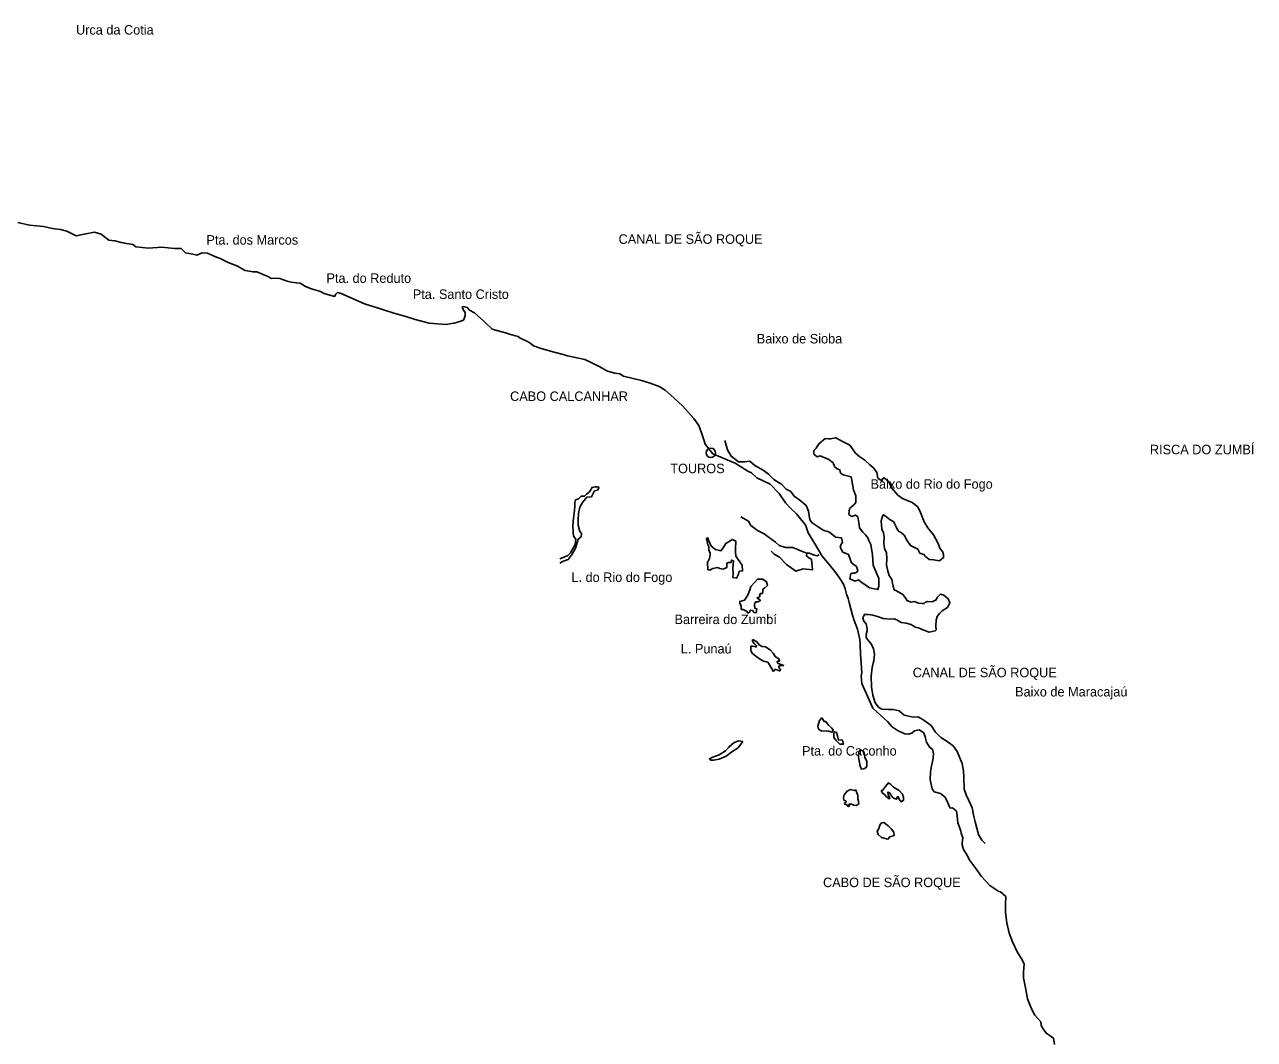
# Model space of a CAD drawing. Extents: x 662444 to 1640468, y 7452018 to 9606170.
# Drawn here: x 1512526 to 1601826, y 9374367 to 9448070 of the extents above; entities that cross this region are included whole.
import ezdxf

# ---------------------------------------------------------------- set-up
doc = ezdxf.new("R2010")
doc.units = 0
for name, color, linetype in [('Level 1', 7, 'Continuous'), ('Level 2', 7, 'Continuous'), ('Level 3', 7, 'Continuous')]:
    doc.layers.add(name, color=color, linetype=linetype)

msp = doc.modelspace()

# ---------------------------------------------------------------- linework, layer by layer
at = {"layer": 'Level 1'}
for points in [[(1520377, 9432099), (1519785, 9432206), (1519542, 9432234), (1519080, 9432354), (1518651, 9432419), (1518079, 9432850), (1517601, 9432988), (1516853, 9432845), (1516274, 9432734), (1515588, 9433061), (1515134, 9433190), (1514558, 9433272), (1513894, 9433397), (1512889, 9433503), (1512046, 9433703)], [(1551627, 9424102), (1550980, 9424279), (1550042, 9424555), (1549476, 9424735), (1549203, 9424960), (1548945, 9425111), (1548501, 9425296), (1548372, 9425413), (1548169, 9425457), (1547806, 9425552), (1547450, 9425672), (1546908, 9425828), (1546487, 9425956), (1545878, 9426520), (1545198, 9427125), (1544834, 9427326), (1544667, 9427517), (1544392, 9427594), (1544302, 9427555), (1544404, 9427326), (1544523, 9427168), (1544527, 9426924), (1544392, 9426592), (1544064, 9426476), (1543689, 9426384), (1543119, 9426287), (1541909, 9426388), (1540897, 9426648), (1540129, 9426905), (1539344, 9427104), (1538374, 9427430), (1537209, 9427798), (1535514, 9428549), (1535239, 9428611), (1535131, 9428482), (1535031, 9428329), (1534279, 9428545), (1534004, 9428688), (1533358, 9428869), (1532929, 9429054), (1532543, 9429297), (1532244, 9429326), (1531878, 9429364), (1531595, 9429425), (1531070, 9429629), (1530802, 9429650), (1530452, 9429639), (1530138, 9429807), (1529395, 9430103), (1529119, 9430107), (1528551, 9430222), (1527947, 9430558), (1527309, 9430788), (1526721, 9431089), (1526341, 9431226), (1525809, 9431478), (1525419, 9431484), (1525034, 9431320), (1524743, 9431389), (1524209, 9431503), (1523888, 9431801), (1523400, 9431809), (1522484, 9431913), (1521524, 9431838), (1520599, 9431917), (1520377, 9432099)], [(1571455, 9408225), (1570849, 9408977), (1570451, 9409465), (1569882, 9410403), (1569415, 9411153), (1569230, 9411742), (1568967, 9412048), (1568568, 9412544), (1568143, 9412942), (1567784, 9413347), (1567308, 9414015), (1566661, 9414694), (1565701, 9415159), (1565317, 9415523), (1565034, 9415642), (1564117, 9416219), (1562510, 9416898), (1561944, 9417592), (1561851, 9417903), (1561689, 9418426), (1561487, 9418952), (1561130, 9419455), (1560332, 9420356), (1559666, 9420953), (1559033, 9421518), (1558615, 9421785), (1557960, 9422024), (1557321, 9422229), (1556009, 9422536), (1555744, 9422695), (1555386, 9422742), (1554860, 9422897), (1554239, 9423233), (1553659, 9423535), (1553207, 9423738), (1551959, 9424011), (1551627, 9424102)], [(1563368, 9417866), (1563558, 9417185), (1563825, 9416722), (1564369, 9416319), (1564833, 9416310), (1565184, 9416352), (1565543, 9416042), (1566146, 9415720), (1566538, 9415426), (1566937, 9415027), (1567507, 9414664), (1567818, 9414339), (1568164, 9414169), (1568401, 9413829), (1568818, 9413519), (1569282, 9413151), (1569444, 9412739), (1569552, 9412099), (1569711, 9411876), (1570521, 9411344), (1570974, 9411197), (1571413, 9410845), (1571835, 9410796), (1571918, 9410450), (1571818, 9410338), (1571756, 9410111), (1571952, 9409763), (1572355, 9409584), (1572578, 9408983), (1572930, 9408706), (1573030, 9408427), (1572946, 9408298), (1572782, 9408235), (1572644, 9408239), (1572513, 9408200), (1572457, 9407817), (1572836, 9407654), (1573074, 9407748), (1573249, 9407589), (1573715, 9407286), (1573883, 9407168), (1574222, 9407087), (1574442, 9407067), (1574490, 9407049), (1574544, 9407285), (1574564, 9407849), (1574276, 9408524), (1574153, 9408813), (1574102, 9409557), (1573964, 9410304), (1573840, 9410592), (1573762, 9410798), (1573588, 9411022), (1573405, 9411205), (1573152, 9411513), (1573102, 9411889), (1573089, 9412029), (1573021, 9412316), (1572854, 9412451), (1572599, 9412349), (1572382, 9412493), (1572416, 9412925), (1572713, 9413156), (1572880, 9413365), (1572890, 9413838), (1572720, 9414275), (1572647, 9414701), (1572536, 9415226), (1571969, 9415368), (1571777, 9415503), (1571725, 9415724), (1571523, 9415810), (1571331, 9415977), (1571247, 9416249), (1570927, 9416492), (1570298, 9416741), (1570077, 9416680), (1569837, 9416881), (1569827, 9417143), (1570008, 9417295), (1570202, 9417617), (1570657, 9418009), (1570892, 9417988), (1571055, 9417993), (1571430, 9418059), (1571970, 9417770), (1572461, 9417516), (1572856, 9416953), (1573168, 9416684), (1573545, 9416424), (1573896, 9416090), (1574183, 9415848), (1574404, 9415533), (1574478, 9415139), (1574654, 9415004), (1574774, 9414937), (1574826, 9415083), (1574941, 9415145), (1575278, 9414870), (1575495, 9414391), (1575941, 9413892)], [(1554248, 9414451), (1554123, 9414266), (1553919, 9414204), (1553700, 9413776), (1553358, 9413749), (1553026, 9413372), (1552842, 9413033), (1552736, 9412553), (1552730, 9412130), (1552722, 9411723), (1552837, 9411265), (1552963, 9411100), (1552935, 9410873), (1552729, 9410689), (1552532, 9410056), (1552297, 9409605), (1551998, 9409218), (1551581, 9409079), (1551398, 9408957)], [(1551403, 9409267), (1551969, 9409503), (1552176, 9409712), (1552503, 9410301), (1552558, 9410691), (1552392, 9410922), (1552349, 9411232), (1552332, 9411656), (1552373, 9412226), (1552455, 9412771), (1552485, 9413120), (1552490, 9413348), (1552518, 9413551), (1552746, 9413637), (1552821, 9413709), (1552936, 9413821), (1553172, 9413826), (1553330, 9413978), (1553551, 9414145), (1553736, 9414460), (1553973, 9414505), (1554094, 9414494), (1554248, 9414451)], [(1575941, 9413892), (1576285, 9413657), (1576987, 9413364), (1577379, 9413039), (1577582, 9412642), (1577853, 9411967), (1578112, 9411528), (1578524, 9411021), (1578846, 9410426), (1579017, 9409998), (1579166, 9409808), (1579260, 9409576), (1579255, 9409364), (1578949, 9409134), (1578527, 9409208), (1578211, 9409221), (1577948, 9409448), (1577828, 9409581), (1577530, 9409693), (1577397, 9409965), (1576849, 9410230), (1576589, 9410627), (1576386, 9410991), (1576209, 9411149), (1575976, 9411285), (1575905, 9411393), (1575811, 9411558), (1575640, 9411945), (1575375, 9412097), (1575135, 9412291), (1574887, 9412475), (1574820, 9412370), (1574731, 9412021), (1574768, 9411432), (1574884, 9411152), (1574935, 9410873), (1574910, 9410416), (1574959, 9410030), (1575107, 9409716), (1575130, 9409258), (1575121, 9408826), (1575200, 9408375), (1575308, 9408063), (1575498, 9407780), (1575579, 9407371), (1575669, 9407025), (1575830, 9406956), (1576297, 9406678), (1576533, 9406362), (1576588, 9406247), (1576895, 9406119), (1577148, 9406179), (1577438, 9406050), (1577697, 9406037), (1577845, 9406034), (1577944, 9406130), (1578115, 9406167), (1578432, 9406145), (1578728, 9406286), (1578797, 9406465), (1579021, 9406713), (1579272, 9406642), (1579599, 9406367), (1579716, 9406078), (1579546, 9405746), (1579158, 9405492), (1578952, 9405300), (1578792, 9405083), (1578714, 9404823), (1578704, 9404374), (1578715, 9404112), (1578648, 9404032), (1578199, 9403935), (1577707, 9404132), (1577498, 9404235), (1577182, 9404314), (1576893, 9404492), (1576537, 9404589), (1576165, 9404638), (1575852, 9404832), (1575657, 9404917), (1575373, 9404890), (1574878, 9404942), (1574450, 9405089), (1574126, 9405177), (1573769, 9405233), (1573510, 9405230), (1573399, 9404980), (1573458, 9404733), (1573625, 9404542), (1573707, 9404172), (1573705, 9404042), (1573642, 9403774), (1573637, 9403545), (1573724, 9403420), (1574002, 9403096), (1574165, 9402742), (1574230, 9402348), (1574180, 9401867), (1574143, 9401703), (1574080, 9401378)], [(1569333, 9409678), (1569050, 9409782), (1568307, 9410096), (1567787, 9410104), (1567325, 9410250), (1567044, 9410475), (1566507, 9410875), (1566217, 9411076), (1565734, 9411336), (1565260, 9411687), (1565079, 9411999), (1564538, 9412310)], [(1562491, 9408562), (1562294, 9408436), (1562132, 9408487), (1562124, 9409001), (1562268, 9409283), (1562312, 9409576), (1562299, 9409715), (1562212, 9409863), (1562201, 9410149), (1562130, 9410297), (1562040, 9410754), (1562106, 9410818), (1562208, 9410588), (1562380, 9410194), (1562701, 9409937), (1563082, 9409848), (1563241, 9410074), (1563441, 9410389), (1563761, 9410571), (1563901, 9410682), (1564167, 9410563), (1564142, 9409994), (1564137, 9409766), (1564173, 9409471), (1564451, 9409060), (1564634, 9408812), (1564659, 9408397), (1564414, 9408368), (1564363, 9408157), (1564227, 9407874), (1563960, 9407903), (1563989, 9408196), (1563963, 9408596), (1563997, 9409124), (1563867, 9409184), (1563832, 9409005), (1563644, 9408992), (1563514, 9408945), (1563516, 9408635), (1563255, 9408526), (1563003, 9408570), (1562842, 9408647), (1562491, 9408562)], [(1570233, 9409550), (1570061, 9409479), (1569746, 9409582), (1569528, 9409675), (1569333, 9409678), (1569305, 9409484), (1569474, 9409342), (1569667, 9409242), (1569744, 9408482), (1569053, 9408543), (1568538, 9408372), (1567854, 9408864), (1567351, 9409394), (1566965, 9409604), (1566741, 9409836)], [(1580645, 9388997), (1580543, 9389339), (1580505, 9389486), (1580413, 9389782), (1580280, 9390085), (1580241, 9390600), (1580189, 9390935), (1579901, 9391176), (1579739, 9391171), (1579605, 9391425), (1579488, 9391713), (1579354, 9391976), (1579041, 9392217), (1578580, 9392348), (1578437, 9392555), (1578323, 9393005), (1578286, 9393233), (1578304, 9393796), (1578385, 9394226), (1578421, 9394430), (1578509, 9394786), (1578523, 9395128), (1578440, 9395440), (1578263, 9395557), (1578017, 9395953), (1577910, 9396346), (1577826, 9396624), (1577495, 9396850), (1577153, 9396774), (1576939, 9396615), (1576686, 9396546), (1576442, 9396550), (1575950, 9396779), (1575587, 9397021), (1575515, 9397079), (1575188, 9397452), (1574444, 9398125), (1574124, 9398433), (1573647, 9399525), (1573325, 9400215), (1573278, 9400745), (1573323, 9400981), (1573262, 9401707), (1573216, 9402319), (1573196, 9403070), (1573186, 9403420), (1573012, 9404157), (1572770, 9404780), (1572639, 9405181), (1572395, 9406099), (1572319, 9406393), (1572202, 9406713), (1572103, 9407098), (1571986, 9407434), (1571725, 9407837), (1571455, 9408225)], [(1565258, 9407270), (1565547, 9407575), (1565746, 9407783), (1566121, 9407801), (1566410, 9407601), (1566478, 9407322), (1566264, 9407147), (1566141, 9407068), (1566120, 9406840), (1566086, 9406743), (1565988, 9406745), (1565891, 9406681), (1565921, 9406599), (1565920, 9406517), (1565814, 9406495), (1565715, 9406423), (1565827, 9406356), (1565916, 9406297), (1565940, 9406240), (1565791, 9406145), (1565621, 9406147), (1565520, 9405994), (1565518, 9405832), (1565571, 9405659), (1565686, 9405650), (1565656, 9405349), (1565502, 9405376), (1565391, 9405516), (1565220, 9405552), (1565219, 9405454), (1565087, 9405350), (1565029, 9405327), (1565000, 9405450), (1564693, 9405584), (1564578, 9405586), (1564548, 9405661), (1564551, 9405848), (1564465, 9406029), (1564467, 9406175), (1564810, 9406259), (1565044, 9406622), (1565206, 9407091), (1565258, 9407270)], [(1567647, 9401518), (1567557, 9401511), (1567371, 9401490), (1567305, 9401483), (1567303, 9401368), (1567423, 9401244), (1567381, 9401138), (1567331, 9401139), (1567073, 9401234), (1566983, 9401243), (1566982, 9401171), (1566876, 9401107), (1566615, 9401568), (1566497, 9401765), (1566172, 9401836), (1565900, 9402004), (1565618, 9402195), (1565393, 9402387), (1565290, 9402551), (1565261, 9402714), (1565272, 9402918), (1565280, 9402918), (1565370, 9402934), (1565541, 9402897), (1565638, 9402863), (1565672, 9402952), (1565536, 9403085), (1565384, 9403259), (1565386, 9403381), (1565444, 9403388), (1565701, 9403246), (1565859, 9403015), (1566094, 9402904), (1566329, 9402884), (1566675, 9402651), (1566891, 9402411), (1567056, 9402163), (1567274, 9402020), (1567345, 9401922), (1567343, 9401840), (1567197, 9401826), (1567171, 9401762), (1567243, 9401663), (1567397, 9401627), (1567647, 9401518)], [(1574080, 9401378), (1574002, 9400742), (1574018, 9399982), (1574120, 9399359), (1574295, 9398808), (1574532, 9398501), (1574781, 9398340), (1575261, 9398332), (1575601, 9398324), (1576030, 9398225), (1576399, 9397924), (1577038, 9397781), (1577404, 9397805), (1577831, 9397559), (1578350, 9397156), (1578674, 9396685), (1579048, 9396301), (1579505, 9396005), (1579962, 9395677), (1580245, 9395271), (1580618, 9394406), (1580696, 9393873), (1580719, 9393423), (1580741, 9392532), (1580895, 9392136), (1581097, 9391707), (1581338, 9391188), (1581383, 9390966), (1581441, 9390645), (1581544, 9390161), (1581794, 9389249), (1582046, 9388843), (1582272, 9388597)], [(1570700, 9397464), (1570907, 9397192), (1571106, 9397001), (1571242, 9396851), (1571174, 9396690), (1570907, 9396759), (1570736, 9396787), (1570411, 9396751), (1570169, 9396902), (1570117, 9397115), (1570253, 9397521), (1570427, 9397713), (1570577, 9397450), (1570700, 9397464)], [(1571636, 9396103), (1571822, 9396117), (1571920, 9396091), (1571996, 9395812), (1571735, 9395809), (1571432, 9396098), (1571282, 9396313), (1571278, 9396574), (1571313, 9396712), (1571483, 9396651), (1571560, 9396415), (1571636, 9396103)], [(1564682, 9396010), (1564341, 9395552), (1563887, 9395242), (1563460, 9394940), (1562968, 9394728), (1562552, 9394637), (1562341, 9394640), (1562252, 9394724), (1562417, 9394835), (1562957, 9395046), (1563418, 9395332), (1563666, 9395596), (1564038, 9395940), (1564381, 9396040), (1564682, 9396010)], [(1573675, 9394585), (1573685, 9394218), (1573600, 9394081), (1573469, 9394009), (1573290, 9394004), (1573188, 9394210), (1573130, 9394602), (1573069, 9394880), (1573101, 9395255), (1573225, 9395399), (1573475, 9395273), (1573503, 9395028), (1573533, 9394840), (1573675, 9394585)], [(1576035, 9392433), (1576267, 9392185), (1576344, 9391939), (1576349, 9391735), (1576176, 9391632), (1576041, 9391822), (1575963, 9391978), (1575898, 9392003), (1575871, 9391874), (1575845, 9391809), (1575620, 9391886), (1575571, 9391944), (1575428, 9392134), (1575341, 9392266), (1575212, 9392333), (1575224, 9392121), (1575296, 9392014), (1575351, 9391858), (1575253, 9391860), (1575197, 9391926), (1575094, 9392017), (1574949, 9392174), (1574813, 9392243), (1574726, 9392439), (1574824, 9392455), (1575032, 9392744), (1575265, 9393009), (1575409, 9392916), (1575617, 9392676), (1576035, 9392433)], [(1572874, 9392488), (1572943, 9392356), (1573029, 9392070), (1573041, 9391833), (1573078, 9391661), (1573091, 9391473), (1572910, 9391354), (1572731, 9391390), (1572571, 9391458), (1572383, 9391461), (1572414, 9391355), (1572372, 9391282), (1572315, 9391299), (1572283, 9391357), (1572188, 9391424), (1572083, 9391442), (1572059, 9391532), (1572109, 9391555), (1572141, 9391555), (1572176, 9391661), (1572014, 9391745), (1571994, 9391940), (1572037, 9392136), (1572253, 9392401), (1572508, 9392519), (1572799, 9392448), (1572874, 9392488)], [(1575234, 9389871), (1575458, 9389655), (1575648, 9389408), (1575677, 9389179), (1575350, 9389086), (1575209, 9388910), (1574756, 9389040), (1574507, 9389248), (1574422, 9389494), (1574564, 9389679), (1574633, 9389939), (1574750, 9390100), (1574922, 9390129), (1575234, 9389871)], [(1583768, 9384740), (1583379, 9385091), (1583266, 9385111), (1582603, 9385541), (1582019, 9386189), (1581588, 9386769), (1581165, 9387365), (1580924, 9387826), (1580706, 9388165), (1580600, 9388501), (1580596, 9388656), (1580645, 9388997)], [(1587311, 9374006), (1587250, 9374455), (1587002, 9374623), (1586698, 9374826), (1586441, 9375215), (1586331, 9375381), (1586322, 9375641), (1585888, 9376132), (1585640, 9376593), (1585358, 9377317), (1585207, 9378103), (1585064, 9378839), (1585067, 9379270), (1585097, 9379832), (1584936, 9380201), (1584632, 9380681), (1584261, 9381446), (1584026, 9382080), (1583843, 9382841), (1583747, 9383584), (1583762, 9384170), (1583768, 9384740)]]:
    msp.add_lwpolyline(points, dxfattribs=at)
at = {"layer": 'Level 2'}
msp.add_ellipse((1562356, 9416966), major_axis=(337, -3), ratio=0.999999, dxfattribs=at)

# ---------------------------------------------------------------- texts
at = {"layer": 'Level 3'}
for s, height, p in [('Urca da Cotia', 689.29, (1516262, 9447344)), ('CANAL DE SÃO ROQUE', 689.88, (1555655, 9432147)), ('Pta. dos Marcos', 689.32, (1525729, 9432090)), ('Pta. do Reduto', 689.45, (1534444, 9429311)), ('Pta. Santo Cristo', 689.56, (1540715, 9428145)), ('Baixo de Sioba', 689.97, (1565691, 9424913)), ('CABO CALCANHAR', 689.6, (1547780, 9420736)), ('RISCA DO ZUMBÍ', 690.41, (1594236, 9416864)), ('TOUROS', 689.7, (1559412, 9415490)), ('Baixo do Rio do Fogo', 690.05, (1573952, 9414362)), ('L. do Rio do Fogo', 689.57, (1552234, 9407590)), ('Barreira do Zumbí', 689.68, (1559716, 9404531)), ('L. Punaú', 689.6, (1560174, 9402397)), ('CANAL DE SÃO ROQUE', 689.96, (1577016, 9400669)), ('Baixo de Maracajaú', 690.08, (1584448, 9399273)), ('Pta. do Caconho', 689.73, (1568979, 9394980)), ('CABO DE SÃO ROQUE', 689.69, (1570503, 9385427))]:
    msp.add_text(s, height=height, dxfattribs=at).set_placement(p)

doc.saveas('drawing.dxf')
